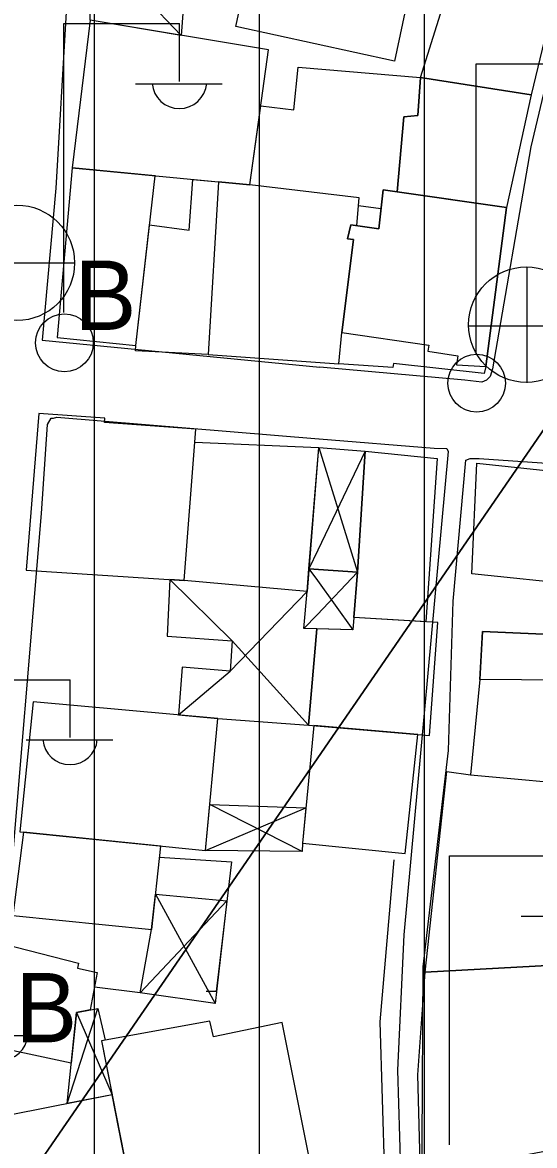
# Model space of a CAD drawing. Extents: x 417997 to 421451, y 4451742 to 4455216.
# Drawn here: x 419667.4 to 419698.4, y 4452806.4 to 4452874.4 of the extents above; entities that cross this region are included whole.
import ezdxf

# ---------------------------------------------------------------- set-up
doc = ezdxf.new("R2010")
doc.units = 0
for name, color, linetype in [('B_Mesken', 7, 'Continuous'), ('B_Sundurma', 7, 'Continuous'), ('B_Teras', 7, 'Continuous'), ('PL_KON_MEV_350', 7, 'Continuous'), ('S_Elektrik_Diregi', 7, 'Continuous'), ('S_Rogar_Kapagi', 7, 'Continuous'), ('S_Rogar_Kapagi_Buski', 7, 'Continuous'), ('Sinir_Duvar_tek_tarafa_ait', 7, 'Continuous'), ('TR_ORTAYOGUNKONUT', 7, 'Continuous'), ('Yol_Sose', 7, 'Continuous')]:
    doc.layers.add(name, color=color, linetype=linetype)

msp = doc.modelspace()

# ---------------------------------------------------------------- linework, layer by layer
at = {"layer": 'B_Mesken'}
for points in [[(419683.283, 4452887.721), (419692.751, 4452885.434), (419689.931, 4452872.105), (419680.321, 4452874.208), (419680.96, 4452877.169)], [(419692.727, 4452885.323), (419701.383, 4452883.253), (419698.216, 4452870.054), (419691.506, 4452871.113), (419692.715, 4452874.974), (419690.632, 4452875.42)], [(419670.408, 4452865.632), (419681.168, 4452864.617), (419682.308, 4452872.782), (419671.49, 4452874.577)], [(419681.836, 4452869.403), (419683.832, 4452869.149), (419684.106, 4452871.741), (419691.506, 4452871.113), (419691.349, 4452868.815), (419690.507, 4452868.734), (419690.102, 4452864.192), (419689.241, 4452864.316), (419689.111, 4452863.161), (419687.751, 4452863.345), (419687.789, 4452863.813), (419681.168, 4452864.617)], [(419698.216, 4452870.054), (419696.719, 4452863.235), (419690.102, 4452864.192), (419690.507, 4452868.734), (419691.349, 4452868.815), (419691.506, 4452871.113)], [(419670.408, 4452865.632), (419669.503, 4452855.352), (419674.261, 4452854.872), (419675.439, 4452865.158)], [(419675.098, 4452862.182), (419677.502, 4452861.859), (419677.724, 4452864.942), (419679.28, 4452864.795), (419678.641, 4452854.326), (419674.251, 4452854.547), (419674.261, 4452854.872)], [(419687.653, 4452862.137), (419687.789, 4452863.813), (419681.168, 4452864.617), (419679.28, 4452864.795), (419678.641, 4452854.326), (419686.569, 4452853.768), (419686.743, 4452855.668), (419687.44, 4452861.294), (419687.09, 4452861.332), (419687.28, 4452862.191)], [(419686.569, 4452853.768), (419686.743, 4452855.668), (419687.44, 4452861.294), (419687.09, 4452861.332), (419687.28, 4452862.191), (419688.975, 4452861.947), (419689.241, 4452864.316), (419696.719, 4452863.235), (419695.459, 4452853.6), (419695.364, 4452853.171), (419689.872, 4452853.782), (419689.837, 4452853.54)], [(419668.382, 4452850.747), (419667.612, 4452841.257), (419677.188, 4452840.647), (419677.893, 4452849.814), (419672.376, 4452850.21), (419672.385, 4452850.481)], [(419677.832, 4452849.021), (419685.336, 4452848.698), (419684.642, 4452839.97), (419677.188, 4452840.647)], [(419688.151, 4452848.476), (419692.522, 4452848.025), (419691.833, 4452838.132), (419687.462, 4452838.387), (419687.681, 4452841.148)], [(419701.553, 4452847.033), (419701.212, 4452840.346), (419694.607, 4452841.048), (419694.927, 4452847.751)], [(419685.232, 4452837.703), (419684.716, 4452831.876), (419692.06, 4452831.256), (419692.555, 4452838.09), (419687.462, 4452838.387), (419687.404, 4452837.651)], [(419695.095, 4452834.633), (419694.528, 4452828.861), (419702.06, 4452828.169), (419706.535, 4452827.663), (419706.63, 4452831.002), (419707.61, 4452830.977), (419708.18, 4452836.981), (419695.269, 4452837.553)], [(419667.239, 4452825.413), (419678.489, 4452824.274), (419679.238, 4452832.281), (419668.048, 4452833.285)], [(419685.051, 4452831.848), (419684.358, 4452824.732), (419690.579, 4452824.095), (419691.343, 4452831.317)], [(419691.794, 4452816.903), (419693.105, 4452829.067), (419694.528, 4452828.861), (419702.06, 4452828.169), (419702.943, 4452828.069), (419702.749, 4452824.414), (419702.385, 4452824.386), (419701.787, 4452817.459)], [(419667.452, 4452825.392), (419666.815, 4452820.337), (419675.231, 4452819.501), (419675.781, 4452824.548)], [(419670.357, 4452811.403), (419664.581, 4452812.623), (419666.231, 4452818.619), (419670.8, 4452817.462), (419670.724, 4452817.145), (419671.93, 4452816.886), (419671.491, 4452814.625), (419670.669, 4452814.463)], [(419701.323, 4452806.959), (419701.462, 4452806.514), (419691.506, 4452804.608), (419691.347, 4452810.699), (419691.794, 4452816.903), (419701.787, 4452817.459), (419701.119, 4452811.724)], [(419684.886, 4452805.07), (419683.127, 4452813.866), (419678.978, 4452812.991), (419678.741, 4452813.951), (419672.188, 4452812.752), (419674.448, 4452801.241), (419684.868, 4452803.38), (419684.872, 4452803.38), (419685.21, 4452803.45), (419684.889, 4452805.053)], [(419672.829, 4452809.484), (419664.756, 4452807.893), (419666.567, 4452799.364), (419674.448, 4452801.241)]]:
    msp.add_lwpolyline(points, close=True, dxfattribs=at)
at = {"layer": 'B_Sundurma'}
for p, q in [((419671.607, 4452879.323), (419677.007, 4452873.661)), ((419688.151, 4452848.476), (419685.284, 4452842.467)), ((419685.353, 4452848.697), (419687.681, 4452841.148)), ((419685.284, 4452842.467), (419684.752, 4452841.353)), ((419684.752, 4452841.353), (419685.264, 4452840.638)), ((419685.242, 4452838.568), (419687.681, 4452841.148)), ((419676.329, 4452840.702), (419680.093, 4452836.993)), ((419685.264, 4452840.638), (419687.404, 4452837.651)), ((419679.978, 4452835.15), (419684.642, 4452839.97)), ((419684.442, 4452837.722), (419685.242, 4452838.568)), ((419680.093, 4452836.993), (419684.716, 4452831.876)), ((419676.854, 4452832.495), (419679.978, 4452835.15)), ((419678.489, 4452824.274), (419684.566, 4452826.872)), ((419684.341, 4452824.216), (419678.75, 4452827.065)), ((419679.782, 4452821.236), (419674.53, 4452815.658)), ((419675.464, 4452821.644), (419679.063, 4452815.01)), ((419670.107, 4452808.948), (419671.953, 4452814.716)), ((419670.669, 4452814.463), (419672.829, 4452809.484))]:
    msp.add_line(p, q, dxfattribs=at)
for points in [[(419671.49, 4452874.577), (419671.607, 4452879.323), (419673.967, 4452878.861), (419673.743, 4452877.838), (419677.27, 4452877.129), (419677.007, 4452873.661)], [(419685.353, 4452848.697), (419688.151, 4452848.476), (419687.681, 4452841.148), (419684.752, 4452841.353)], [(419684.442, 4452837.722), (419684.642, 4452839.97), (419684.752, 4452841.353), (419687.681, 4452841.148), (419687.404, 4452837.651)], [(419676.329, 4452840.702), (419676.163, 4452837.257), (419680.093, 4452836.993), (419679.978, 4452835.15), (419677.079, 4452835.38), (419676.854, 4452832.495), (419679.238, 4452832.281), (419684.716, 4452831.876), (419685.232, 4452837.703), (419684.442, 4452837.722), (419684.642, 4452839.97), (419677.188, 4452840.647)], [(419684.358, 4452824.732), (419684.341, 4452824.216), (419678.489, 4452824.274), (419678.75, 4452827.065), (419684.566, 4452826.872)], [(419675.464, 4452821.644), (419679.782, 4452821.236), (419679.063, 4452815.01), (419674.53, 4452815.658), (419675.205, 4452819.504)], [(419670.107, 4452808.948), (419670.669, 4452814.463), (419671.953, 4452814.716), (419672.414, 4452812.794), (419672.188, 4452812.752), (419672.829, 4452809.484)]]:
    msp.add_lwpolyline(points, close=True, dxfattribs=at)
at = {"layer": 'B_Teras'}
for points in [[(419687.28, 4452862.191), (419687.09, 4452861.332), (419687.44, 4452861.294), (419686.743, 4452855.668), (419692.015, 4452854.902), (419691.949, 4452854.526), (419693.777, 4452854.25), (419693.679, 4452853.712), (419695.459, 4452853.6), (419696.719, 4452863.235), (419689.241, 4452864.316), (419688.975, 4452861.947)], [(419695.095, 4452834.633), (419695.269, 4452837.553), (419708.18, 4452836.981), (419707.61, 4452830.977), (419706.63, 4452831.002), (419706.535, 4452827.663), (419702.06, 4452828.169), (419702.688, 4452834.576)]]:
    msp.add_lwpolyline(points, close=True, dxfattribs=at)
at = {"layer": 'PL_KON_MEV_350'}
msp.add_lwpolyline([(419796.331, 4452996.105), (419805.412, 4452988.482), (419786.294, 4452689.029), (419775.978, 4452676.538), (419568.876, 4452622.815), (419561.752, 4452629.972), (419581.871, 4452706.077), (419635.792, 4452719.454), (419637.405, 4452760.32), (419700.317, 4452851.73), (419754.087, 4452844.74), (419741.182, 4452876.464), (419703.543, 4452885.605), (419700.317, 4452851.73), (419637.405, 4452760.32), (419580.562, 4452749.662), (419577.387, 4452855.396), (419570.344, 4452931.114), (419579.136, 4452943.428)], close=True, dxfattribs=at)
at = {"layer": 'S_Elektrik_Diregi'}
for p, q in [((419669.903, 4452856.875), (419669.903, 4452874.375)), ((419669.903, 4452874.375), (419676.903, 4452874.375)), ((419676.903, 4452870.875), (419676.903, 4452874.375)), ((419694.872, 4452854.43), (419694.871, 4452871.93)), ((419694.871, 4452871.93), (419701.872, 4452871.93)), ((419674.243, 4452870.735), (419679.493, 4452870.735)), ((419663.277, 4452834.627), (419670.277, 4452834.627)), ((419670.277, 4452831.127), (419670.277, 4452834.627)), ((419667.617, 4452830.987), (419672.867, 4452830.987)), ((419693.262, 4452806.45), (419693.262, 4452823.95)), ((419693.262, 4452823.95), (419700.262, 4452823.95)), ((419697.602, 4452820.31), (419702.852, 4452820.31)), ((419663.409, 4452813.075), (419668.659, 4452813.075))]:
    msp.add_line(p, q, dxfattribs=at)
for centre in [(419669.939, 4452855.04), (419694.907, 4452852.594)]:
    msp.add_circle(centre, 1.75, dxfattribs=at)
for centre in [(419676.903, 4452870.888), (419670.278, 4452831.14), (419666.069, 4452813.228)]:
    msp.add_arc(centre, 1.658, 184.83843, 355.14641, dxfattribs=at)
at = {"layer": 'S_Rogar_Kapagi'}
for p, q in [((419697.974, 4452852.607), (419697.974, 4452859.607)), ((419694.404, 4452856.072), (419701.404, 4452856.072))]:
    msp.add_line(p, q, dxfattribs=at)
msp.add_circle((419697.921, 4452856.136), 3.5, dxfattribs=at)
at = {"layer": 'S_Rogar_Kapagi_Buski'}
msp.add_line((419663.553, 4452859.884), (419670.553, 4452859.884), dxfattribs=at)
msp.add_circle((419667.053, 4452859.884), 3.5, dxfattribs=at)
at = {"layer": 'Sinir_Duvar_tek_tarafa_ait'}
for points in [[(419675.707, 4452823.872), (419680.062, 4452823.589), (419679.128, 4452815.739), (419678.534, 4452815.737)], [(419689.899, 4452823.722), (419689.034, 4452813.906), (419689.336, 4452804.525), (419687.686, 4452804.166)], [(419674.53, 4452815.658), (419671.76, 4452816.011)]]:
    msp.add_lwpolyline(points, dxfattribs=at)
at = {"layer": 'TR_ORTAYOGUNKONUT'}
for p, q in [((419691.752, 4452654.69), (419691.752, 4452970.741)), ((419691.752, 4452654.69), (419691.752, 4452970.741)), ((419681.752, 4452652.096), (419681.752, 4452968.316)), ((419681.752, 4452652.096), (419681.752, 4452968.316)), ((419671.752, 4452649.502), (419671.752, 4452965.891)), ((419671.752, 4452649.502), (419671.752, 4452965.891))]:
    msp.add_line(p, q, dxfattribs=at)
at = {"layer": 'Yol_Sose'}
for points in [[(419685.765, 4452887.711), (419675.808, 4452889.774), (419672.566, 4452890.583), (419670.94, 4452881.908), (419670.05, 4452875.065), (419669.411, 4452864.415), (419668.587, 4452855.189), (419685.402, 4452853.56)], [(419701.17, 4452883.989), (419701.871, 4452883.779), (419701.999, 4452883.521), (419701.93, 4452882.663), (419698.196, 4452866.908), (419695.87, 4452853.458), (419695.728, 4452853.007), (419695.499, 4452852.775), (419695.213, 4452852.656), (419694.189, 4452852.771)], [(419685.405, 4452853.56), (419685.402, 4452853.56)], [(419685.402, 4452853.56), (419685.405, 4452853.56)], [(419694.189, 4452852.771), (419685.405, 4452853.56)], [(419666.555, 4452820.792), (419668.556, 4452844.693), (419668.922, 4452850.086), (419669.135, 4452850.464), (419669.286, 4452850.478), (419669.483, 4452850.538), (419685.356, 4452849.229)], [(419685.356, 4452849.229), (419685.359, 4452849.229)], [(419685.359, 4452849.229), (419692.342, 4452848.653)], [(419692.342, 4452848.653), (419693.108, 4452848.628), (419693.176, 4452848.455), (419690.502, 4452819.164), (419690.118, 4452810.965), (419690.29, 4452804.906), (419690.213, 4452804.539), (419690.049, 4452804.2), (419689.696, 4452803.871)], [(419716.278, 4452809.564), (419693.48, 4452804.406), (419692.813, 4452804.38), (419692.183, 4452804.454), (419691.589, 4452804.833), (419691.616, 4452806.533), (419691.669, 4452817.241), (419693.201, 4452830.336), (419693.492, 4452839.383), (419694.253, 4452847.936), (419694.508, 4452848.035), (419695.063, 4452848.032), (419715.817, 4452846.598), (419742.801, 4452844.313), (419754.178, 4452843.273), (419754.693, 4452842.805), (419755.021, 4452842.183), (419757.107, 4452833.888), (419758.587, 4452819.286), (419758.397, 4452818.876), (419758.106, 4452818.685), (419757.044, 4452818.351), (419749.854, 4452816.537)]]:
    msp.add_lwpolyline(points, dxfattribs=at)

# ---------------------------------------------------------------- texts
at = {"layer": 'S_Rogar_Kapagi_Buski'}
for p in [(419670.553, 4452855.82), (419666.963, 4452812.661)]:
    msp.add_text('B', height=4.2, dxfattribs=at).set_placement(p)

doc.saveas('drawing.dxf')
